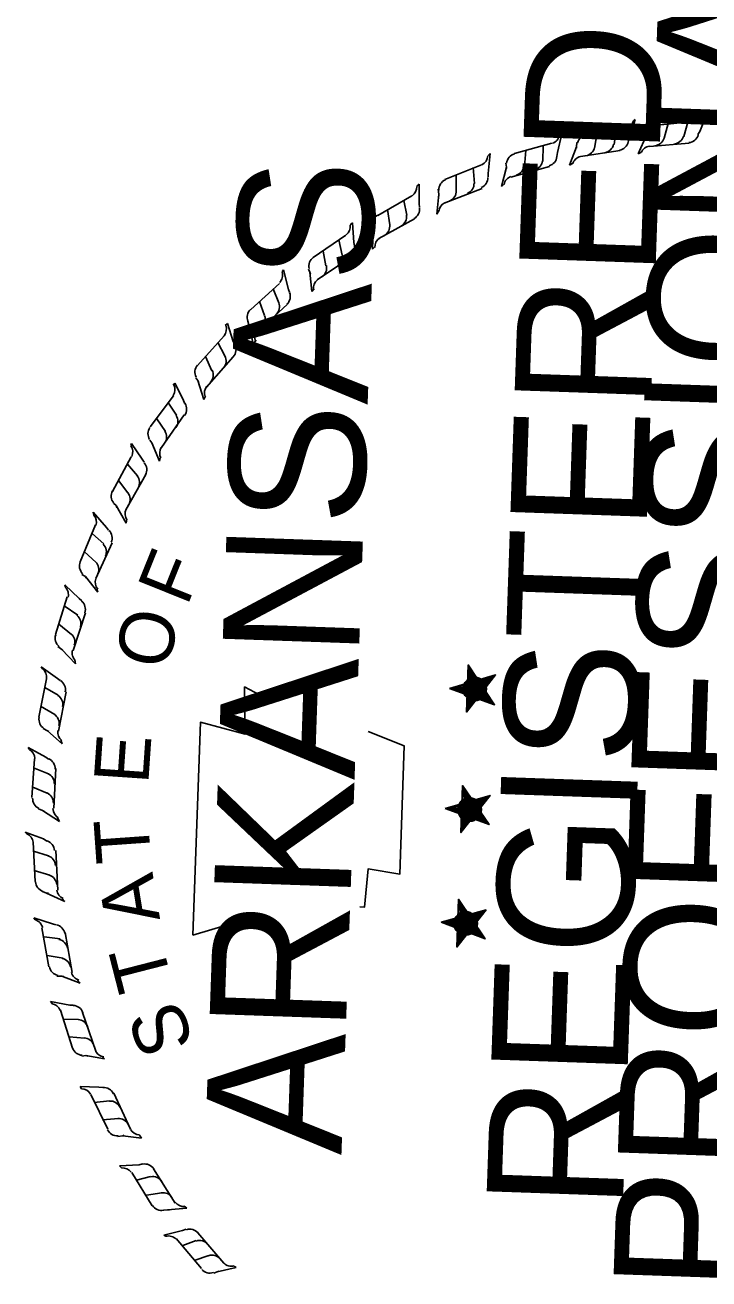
# Model space of a CAD drawing. Extents: x 634032 to 635126, y 289804 to 291423.
# Drawn here: x 634402.1 to 634451.4, y 289860.1 to 289950.5 of the extents above; entities that cross this region are included whole.
import ezdxf

# ---------------------------------------------------------------- set-up
doc = ezdxf.new("R2010")
doc.units = 0
doc.layers.add('Level 1', color=7, linetype='Continuous')

msp = doc.modelspace()

# ---------------------------------------------------------------- linework, layer by layer
at = {"layer": 'Level 1'}
for p, q in [((634445.657, 289942.332), (634446.054, 289943.669)), ((634446.054, 289943.669), (634445.951, 289943.573)), ((634447.641, 289943.264), (634450.503, 289943.564)), ((634449.563, 289942.446), (634449.85, 289943.487)), ((634450.727, 289942.806), (634451.222, 289944.089)), ((634451.222, 289944.089), (634451.072, 289944.094)), ((634440.468, 289941.313), (634440.765, 289942.653)), ((634440.765, 289942.653), (634440.612, 289942.558)), ((634442.614, 289942.589), (634445.382, 289943.042)), ((634443.131, 289941.62), (634443.319, 289942.714)), ((634444.54, 289941.871), (634444.679, 289942.967)), ((634446.865, 289942.54), (634446.268, 289941.21)), ((634446.865, 289942.54), (634446.86, 289942.39)), ((634446.874, 289942.79), (634446.865, 289942.54)), ((634448.159, 289942.345), (634448.446, 289943.386)), ((634450.57, 289942.611), (634450.727, 289942.806)), ((634437.363, 289941.221), (634440.041, 289941.978)), ((634439.395, 289940.65), (634439.435, 289941.799)), ((634441.833, 289941.715), (634441.336, 289940.382)), ((634441.833, 289941.715), (634441.83, 289941.615)), ((634441.844, 289942.015), (634441.833, 289941.715)), ((634445.548, 289942.086), (634445.657, 289942.332)), ((634449.947, 289941.982), (634447.087, 289941.732)), ((634435.613, 289941.232), (634435.457, 289941.087)), ((634435.462, 289939.786), (634435.613, 289941.232)), ((634438.081, 289940.295), (634438.171, 289941.443)), ((634440.408, 289941.015), (634440.468, 289941.313)), ((634444.976, 289941.455), (634442.109, 289941.005)), ((634446.268, 289941.21), (634446.472, 289941.303)), ((634432.345, 289939.345), (634434.983, 289940.404)), ((634434.486, 289939.07), (634434.377, 289940.225)), ((634436.779, 289940.241), (634436.43, 289938.852)), ((634436.739, 289940.542), (634436.779, 289940.241)), ((634436.779, 289940.241), (634436.775, 289940.141)), ((634439.882, 289940.282), (634437.104, 289939.529)), ((634441.336, 289940.382), (634441.591, 289940.523)), ((634430.482, 289939.01), (634430.327, 289938.865)), ((634430.483, 289937.609), (634430.482, 289939.01)), ((634433.166, 289938.516), (634433.158, 289939.717)), ((634435.453, 289939.537), (634435.462, 289939.786)), ((634436.43, 289938.852), (634436.637, 289939.045)), ((634427.502, 289936.762), (634429.953, 289938.178)), ((634431.908, 289938.31), (634431.758, 289936.864)), ((634431.871, 289938.661), (634431.908, 289938.31)), ((634431.908, 289938.31), (634431.903, 289938.16)), ((634435.024, 289938.701), (634432.285, 289937.646)), ((634428.378, 289936.081), (634428.217, 289937.188)), ((634429.604, 289936.789), (634429.391, 289937.847)), ((634430.524, 289937.357), (634430.483, 289937.609)), ((634425.682, 289936.226), (634425.527, 289936.081)), ((634425.783, 289934.821), (634425.682, 289936.226)), ((634430.145, 289936.52), (634427.594, 289935.108)), ((634431.758, 289936.864), (634431.916, 289937.109)), ((634422.843, 289933.723), (634425.201, 289935.342)), ((634427.074, 289935.977), (634427.165, 289935.724)), ((634427.165, 289935.724), (634427.116, 289934.324)), ((634427.165, 289935.724), (634427.16, 289935.574)), ((634424.95, 289933.9), (634424.689, 289935.01)), ((634425.824, 289934.57), (634425.783, 289934.821)), ((634427.116, 289934.324), (634427.323, 289934.517)), ((634425.545, 289933.729), (634423.137, 289932.112)), ((634423.773, 289933.14), (634423.56, 289934.198)), ((634420.711, 289932.847), (634420.606, 289932.701)), ((634421.062, 289931.434), (634420.711, 289932.847)), ((634422.513, 289932.884), (634422.606, 289932.681)), ((634422.606, 289932.681), (634422.757, 289931.275)), ((634422.606, 289932.681), (634422.651, 289932.529)), ((634418.359, 289929.977), (634420.426, 289931.856)), ((634420.377, 289930.457), (634419.962, 289931.472)), ((634421.155, 289931.231), (634421.062, 289931.434)), ((634422.757, 289931.275), (634422.914, 289931.469)), ((634420.973, 289930.336), (634418.803, 289928.361)), ((634419.345, 289929.543), (634418.98, 289930.556)), ((634416.674, 289928.986), (634416.518, 289928.841)), ((634417.078, 289927.671), (634416.674, 289928.986)), ((634418.13, 289929.135), (634418.221, 289928.881)), ((634414.517, 289925.959), (634416.442, 289928.093)), ((634418.221, 289928.881), (634418.524, 289927.52)), ((634418.221, 289928.881), (634418.316, 289928.728)), ((634416.492, 289926.64), (634415.975, 289927.609)), ((634417.221, 289927.466), (634417.078, 289927.671)), ((634418.524, 289927.52), (634418.732, 289927.763)), ((634415.554, 289925.573), (634415.089, 289926.589)), ((634417.09, 289926.57), (634415.162, 289924.386)), ((634412.871, 289924.666), (634412.765, 289924.519)), ((634413.48, 289923.494), (634412.871, 289924.666)), ((634414.385, 289925.063), (634414.528, 289924.858)), ((634414.528, 289924.858), (634414.981, 289923.491)), ((634414.528, 289924.858), (634414.575, 289924.756)), ((634411.11, 289921.525), (634412.789, 289923.768)), ((634414.981, 289923.491), (634415.09, 289923.738)), ((634412.99, 289922.36), (634412.42, 289923.23)), ((634413.571, 289923.24), (634413.48, 289923.494)), ((634412.199, 289921.187), (634411.581, 289922.109)), ((634413.542, 289922.391), (634411.909, 289920.046)), ((634409.767, 289920.321), (634409.712, 289920.173)), ((634410.528, 289919.194), (634409.767, 289920.321)), ((634411.077, 289920.576), (634411.22, 289920.371)), ((634411.22, 289920.371), (634411.774, 289919.051)), ((634411.22, 289920.371), (634411.266, 289920.269)), ((634408.396, 289916.867), (634409.734, 289919.372)), ((634410.671, 289918.989), (634410.528, 289919.194)), ((634411.774, 289919.051), (634411.833, 289919.299)), ((634410.186, 289918.005), (634409.465, 289918.831)), ((634409.493, 289916.779), (634408.823, 289917.653)), ((634410.79, 289918.084), (634409.35, 289915.533)), ((634408.466, 289916.014), (634408.661, 289915.857)), ((634408.661, 289915.857), (634409.366, 289914.582)), ((634408.661, 289915.857), (634408.705, 289915.706)), ((634407.955, 289914.281), (634406.992, 289915.365)), ((634406.992, 289915.365), (634407.035, 289915.164)), ((634409.366, 289914.582), (634409.427, 289914.88)), ((634406.067, 289911.795), (634407.161, 289914.459)), ((634407.763, 289913.087), (634406.938, 289913.816)), ((634408.098, 289914.076), (634407.955, 289914.281)), ((634408.366, 289913.166), (634407.176, 289910.606)), ((634407.217, 289911.755), (634406.343, 289912.536)), ((634405.975, 289909.147), (634404.959, 289910.133)), ((634404.959, 289910.133), (634405.003, 289909.981)), ((634406.186, 289910.891), (634406.43, 289910.732)), ((634406.43, 289910.732), (634407.341, 289909.599)), ((634406.43, 289910.732), (634406.477, 289910.63)), ((634404.283, 289906.554), (634405.129, 289909.276)), ((634406.169, 289908.99), (634405.975, 289909.147)), ((634407.341, 289909.599), (634407.25, 289909.853)), ((634405.883, 289907.949), (634404.906, 289908.634)), ((634405.434, 289906.564), (634404.509, 289907.297)), ((634406.44, 289908.13), (634405.544, 289905.41)), ((634404.453, 289905.698), (634404.746, 289905.488)), ((634404.746, 289905.488), (634405.711, 289904.453)), ((634404.746, 289905.488), (634404.795, 289905.436)), ((634405.711, 289904.453), (634405.67, 289904.705)), ((634404.423, 289903.398), (634403.252, 289904.239)), ((634403.252, 289904.239), (634403.347, 289904.085)), ((634434.025, 289904.365), (634434.514, 289902.597)), ((634434.025, 289904.365), (634434.071, 289902.812)), ((634434.025, 289904.365), (634434.176, 289902.959)), ((634434.025, 289904.365), (634434.276, 289902.955)), ((634434.025, 289904.365), (634434.386, 289903.252)), ((634434.025, 289904.365), (634434.49, 289903.348)), ((634434.025, 289904.365), (634434.541, 289903.396)), ((634403.074, 289900.593), (634403.622, 289903.375)), ((634404.618, 289903.241), (634404.423, 289903.398)), ((634432.665, 289902.661), (634433.928, 289903.018)), ((634432.665, 289902.661), (634433.924, 289902.918)), ((634436.001, 289903.646), (634434.514, 289902.597)), ((634436.001, 289903.646), (634434.527, 289902.997)), ((634436.001, 289903.646), (634434.533, 289903.147)), ((634436.001, 289903.646), (634434.727, 289902.99)), ((634436.001, 289903.646), (634434.913, 289902.583)), ((634436.001, 289903.646), (634434.92, 289902.783)), ((634436.001, 289903.646), (634435.063, 289902.578)), ((634404.481, 289902.195), (634403.499, 289902.729)), ((634405.04, 289902.425), (634404.49, 289899.593)), ((634432.665, 289902.661), (634433.919, 289902.768)), ((634434.514, 289902.597), (634432.665, 289902.661)), ((634432.665, 289902.661), (634433.912, 289902.568)), ((634432.665, 289902.661), (634433.909, 289902.468)), ((634432.665, 289902.661), (634433.905, 289902.368)), ((634433.906, 289900.967), (634434.514, 289902.597)), ((634433.906, 289900.967), (634434.05, 289902.213)), ((634433.906, 289900.967), (634434.15, 289902.209)), ((634433.906, 289900.967), (634434.246, 289902.106)), ((634433.906, 289900.967), (634434.396, 289902.101)), ((634433.906, 289900.967), (634434.494, 289902.047)), ((634433.906, 289900.967), (634434.644, 289902.042)), ((634435.926, 289901.497), (634434.514, 289902.597)), ((634435.926, 289901.497), (634434.596, 289902.094)), ((634435.926, 289901.497), (634434.699, 289902.19)), ((634435.926, 289901.497), (634434.753, 289902.288)), ((634435.926, 289901.497), (634434.908, 289902.433)), ((634435.926, 289901.497), (634434.913, 289902.583)), ((634435.926, 289901.497), (634435.015, 289902.629)), ((634404.232, 289900.803), (634403.202, 289901.389)), ((634403.396, 289899.781), (634403.691, 289899.621)), ((634403.691, 289899.621), (634404.759, 289898.683)), ((634403.691, 289899.621), (634403.789, 289899.567)), ((634403.575, 289897.724), (634402.298, 289898.419)), ((634402.298, 289898.419), (634402.393, 289898.265)), ((634404.759, 289898.683), (634404.668, 289898.936)), ((634402.572, 289894.807), (634402.77, 289897.602)), ((634403.769, 289897.567), (634403.575, 289897.724)), ((634403.783, 289896.516), (634402.697, 289896.954)), ((634404.296, 289896.898), (634404.147, 289894.051)), ((634403.684, 289895.118), (634402.648, 289895.555)), ((634433.621, 289895.674), (634434.112, 289893.956)), ((634433.621, 289895.674), (634433.669, 289894.171)), ((634433.621, 289895.674), (634433.872, 289894.264)), ((634433.621, 289895.674), (634433.922, 289894.262)), ((634433.621, 289895.674), (634434.083, 289894.557)), ((634433.621, 289895.674), (634434.086, 289894.657)), ((634433.621, 289895.674), (634434.188, 289894.703)), ((634435.597, 289894.954), (634434.112, 289893.956)), ((634435.597, 289894.954), (634434.174, 289894.304)), ((634435.597, 289894.954), (634434.179, 289894.454)), ((634435.597, 289894.954), (634434.424, 289894.295)), ((634435.597, 289894.954), (634434.56, 289893.89)), ((634435.597, 289894.954), (634434.567, 289894.09)), ((634435.597, 289894.954), (634434.66, 289893.886)), ((634403.044, 289893.99), (634403.34, 289893.879)), ((634403.34, 289893.879), (634404.563, 289893.086)), ((634403.34, 289893.879), (634403.439, 289893.826)), ((634432.363, 289894.017), (634433.574, 289894.325)), ((634432.363, 289894.017), (634433.571, 289894.225)), ((634432.363, 289894.017), (634433.566, 289894.075)), ((634434.112, 289893.956), (634432.363, 289894.017)), ((634432.363, 289894.017), (634433.559, 289893.875)), ((634432.363, 289894.017), (634433.555, 289893.775)), ((634432.363, 289894.017), (634433.502, 289893.677)), ((634433.503, 289892.276), (634434.112, 289893.956)), ((634435.524, 289892.856), (634434.112, 289893.956)), ((634435.524, 289892.856), (634434.51, 289893.892)), ((634435.524, 289892.856), (634434.554, 289893.74)), ((634435.524, 289892.856), (634434.661, 289893.936)), ((634404.563, 289893.086), (634404.422, 289893.341)), ((634433.503, 289892.276), (634433.696, 289893.52)), ((634433.503, 289892.276), (634433.794, 289893.466)), ((634433.503, 289892.276), (634433.844, 289893.465)), ((634433.503, 289892.276), (634434.043, 289893.408)), ((634433.503, 289892.276), (634434.191, 289893.353)), ((634433.503, 289892.276), (634434.291, 289893.349)), ((634435.524, 289892.856), (634434.194, 289893.452)), ((634435.524, 289892.856), (634434.396, 289893.495)), ((634435.524, 289892.856), (634434.399, 289893.595)), ((634403.419, 289891.826), (634402.085, 289892.322)), ((634402.085, 289892.322), (634402.23, 289892.167)), ((634402.811, 289888.745), (634402.66, 289891.602)), ((634403.663, 289891.667), (634403.419, 289891.826)), ((634403.777, 289890.612), (634402.688, 289890.95)), ((634404.29, 289890.995), (634404.441, 289888.138)), ((634403.878, 289889.208), (634402.739, 289889.548)), ((634403.336, 289888.026), (634403.632, 289887.916)), ((634403.632, 289887.916), (634404.962, 289887.319)), ((634403.632, 289887.916), (634403.782, 289887.91)), ((634404.962, 289887.319), (634404.769, 289887.526)), ((634433.335, 289887.479), (634433.826, 289885.761)), ((634433.335, 289887.479), (634433.383, 289885.976)), ((634433.335, 289887.479), (634433.586, 289886.069)), ((634433.335, 289887.479), (634433.636, 289886.067)), ((634433.335, 289887.479), (634433.797, 289886.362)), ((634433.335, 289887.479), (634433.8, 289886.462)), ((634433.335, 289887.479), (634433.902, 289886.508)), ((634435.31, 289886.709), (634433.826, 289885.761)), ((634435.31, 289886.709), (634433.888, 289886.109)), ((634435.31, 289886.709), (634433.891, 289886.209)), ((634435.31, 289886.709), (634434.136, 289886.05)), ((634435.31, 289886.709), (634434.275, 289885.745)), ((634435.31, 289886.709), (634434.281, 289885.895)), ((634435.31, 289886.709), (634434.375, 289885.741)), ((634404.055, 289885.7), (634402.72, 289886.146)), ((634402.72, 289886.146), (634402.815, 289885.993)), ((634404.303, 289885.641), (634404.055, 289885.7)), ((634432.077, 289885.822), (634433.286, 289886.08)), ((634432.077, 289885.822), (634433.283, 289885.98)), ((634432.077, 289885.822), (634433.279, 289885.88)), ((634433.826, 289885.761), (634432.077, 289885.822)), ((634432.077, 289885.822), (634433.272, 289885.68)), ((634432.077, 289885.822), (634433.269, 289885.58)), ((634432.077, 289885.822), (634433.215, 289885.482)), ((634433.215, 289884.031), (634433.826, 289885.761)), ((634435.236, 289884.611), (634433.826, 289885.761)), ((634435.236, 289884.611), (634434.225, 289885.747)), ((634435.236, 289884.611), (634434.375, 289885.741)), ((634403.797, 289882.607), (634403.295, 289885.426)), ((634404.618, 289884.629), (634403.472, 289884.769)), ((634404.984, 289885.067), (634405.484, 289882.198)), ((634433.215, 289884.031), (634433.408, 289885.275)), ((634433.215, 289884.031), (634433.508, 289885.271)), ((634433.215, 289884.031), (634433.556, 289885.22)), ((634433.215, 289884.031), (634433.756, 289885.213)), ((634433.215, 289884.031), (634433.906, 289885.207)), ((634433.215, 289884.031), (634434.006, 289885.204)), ((634435.236, 289884.611), (634433.906, 289885.207)), ((634435.236, 289884.611), (634434.11, 289885.3)), ((634435.236, 289884.611), (634434.113, 289885.4)), ((634435.236, 289884.611), (634434.268, 289885.545)), ((634404.819, 289883.221), (634403.675, 289883.411)), ((634404.374, 289881.936), (634404.724, 289881.924)), ((634404.724, 289881.924), (634406.057, 289881.427)), ((634404.724, 289881.924), (634404.874, 289881.919)), ((634406.057, 289881.427), (634405.864, 289881.634)), ((634405.302, 289879.852), (634403.91, 289880.101)), ((634403.91, 289880.101), (634404.054, 289879.946)), ((634405.494, 289876.744), (634404.638, 289879.475)), ((634405.552, 289879.844), (634405.302, 289879.852)), ((634406.234, 289879.32), (634407.187, 289876.535)), ((634405.917, 289878.83), (634404.816, 289878.819)), ((634406.369, 289877.464), (634405.272, 289877.552)), ((634406.174, 289876.17), (634406.476, 289876.209)), ((634406.476, 289876.209), (634407.818, 289875.962)), ((634406.476, 289876.209), (634406.624, 289876.154)), ((634407.818, 289875.962), (634407.673, 289876.117)), ((634407.396, 289873.926), (634406.047, 289873.973)), ((634406.047, 289873.973), (634406.142, 289873.82)), ((634407.696, 289873.915), (634407.396, 289873.926)), ((634408.041, 289870.901), (634406.828, 289873.395)), ((634408.163, 289872.948), (634407.058, 289872.837)), ((634408.482, 289873.488), (634409.692, 289870.894)), ((634408.819, 289871.675), (634407.664, 289871.565)), ((634408.773, 289870.376), (634409.125, 289870.413)), ((634409.125, 289870.413), (634409.227, 289870.46)), ((634409.125, 289870.413), (634410.471, 289870.266)), ((634410.471, 289870.266), (634410.328, 289870.471)), ((634410.303, 289868.321), (634408.9, 289868.27)), ((634408.9, 289868.27), (634409.045, 289868.115)), ((634411.251, 289865.386), (634409.784, 289867.789)), ((634410.556, 289868.412), (634410.303, 289868.321)), ((634411.343, 289868.034), (634412.908, 289865.578)), ((634411.124, 289867.492), (634410.114, 289867.227)), ((634411.933, 289866.313), (634410.827, 289866.151)), ((634412.09, 289865.057), (634412.341, 289865.098)), ((634412.341, 289865.098), (634413.746, 289865.199)), ((634412.341, 289865.098), (634412.491, 289865.093)), ((634413.746, 289865.199), (634413.551, 289865.356)), ((634413.44, 289863.609), (634412.077, 289863.256)), ((634412.077, 289863.256), (634412.225, 289863.201)), ((634414.795, 289860.86), (634412.969, 289863.025)), ((634413.693, 289863.7), (634413.44, 289863.609)), ((634414.534, 289863.42), (634416.41, 289861.254)), ((634414.415, 289862.874), (634413.452, 289862.508)), ((634415.328, 289861.792), (634414.264, 289861.428)), ((634415.684, 289860.528), (634415.937, 289860.62)), ((634415.937, 289860.62), (634417.299, 289860.922)), ((634415.937, 289860.62), (634416.039, 289860.666)), ((634417.299, 289860.922), (634417.152, 289861.027))]:
    msp.add_line(p, q, dxfattribs=at)
for points in [[(634432.665, 289902.661), (634436.001, 289903.646), (634433.906, 289900.967), (634434.025, 289904.365), (634435.926, 289901.497), (634432.665, 289902.661)], [(634419.334, 289902.026), (634417.91, 289902.776), (634417.941, 289899.373), (634414.719, 289900.236), (634414.183, 289884.896)], [(634426.212, 289886.927), (634426.561, 289886.915), (634426.807, 289889.658), (634429.095, 289889.278), (634429.418, 289898.522), (634426.803, 289899.564)], [(634432.363, 289894.017), (634435.597, 289894.954), (634433.503, 289892.276), (634433.621, 289895.674), (634435.524, 289892.856), (634432.363, 289894.017)], [(634432.077, 289885.822), (634435.31, 289886.709), (634433.215, 289884.031), (634433.335, 289887.479), (634435.236, 289884.611), (634432.077, 289885.822)], [(634414.183, 289884.896), (634418.278, 289886.103)]]:
    msp.add_lwpolyline(points, dxfattribs=at)
for centre, radius in [((634434.49, 289902.631), 0.848), ((634434.49, 289902.631), 0.767), ((634434.49, 289902.631), 0.711), ((634434.49, 289902.631), 0.653), ((634434.49, 289902.631), 0.57), ((634434.49, 289902.631), 0.529), ((634434.49, 289902.631), 0.488), ((634434.49, 289902.631), 0.42), ((634434.49, 289902.631), 0.368), ((634434.49, 289902.631), 0.306), ((634434.49, 289902.631), 0.244), ((634434.49, 289902.631), 0.182), ((634434.49, 289902.631), 0.146), ((634434.49, 289902.631), 0.071), ((634434.129, 289893.941), 0.848), ((634434.129, 289893.941), 0.767), ((634434.129, 289893.941), 0.711), ((634434.129, 289893.941), 0.653), ((634434.129, 289893.941), 0.57), ((634434.129, 289893.941), 0.529), ((634434.129, 289893.941), 0.488), ((634434.129, 289893.941), 0.42), ((634434.129, 289893.941), 0.368), ((634434.129, 289893.941), 0.306), ((634434.129, 289893.941), 0.244), ((634434.129, 289893.941), 0.182), ((634434.129, 289893.941), 0.146), ((634434.129, 289893.941), 0.071), ((634433.842, 289885.732), 0.848), ((634433.842, 289885.732), 0.767), ((634433.842, 289885.732), 0.711), ((634433.842, 289885.732), 0.653), ((634433.842, 289885.732), 0.57), ((634433.842, 289885.732), 0.529), ((634433.842, 289885.732), 0.488), ((634433.842, 289885.732), 0.42), ((634433.842, 289885.732), 0.368), ((634433.842, 289885.732), 0.306), ((634433.842, 289885.732), 0.244), ((634433.842, 289885.732), 0.182), ((634433.842, 289885.732), 0.146), ((634433.842, 289885.732), 0.071)]:
    msp.add_circle(centre, radius, dxfattribs=at)
for centre, start, end in [((634445.176, 289943.815), 283.79119, 342.57904), ((634450.354, 289944.332), 279.43481, 338.22265), ((634439.84, 289942.699), 290.09384, 348.88168), ((634442.673, 289941.836), 99.53042, 167.90439), ((634447.708, 289942.548), 95.17403, 163.548), ((634449.862, 289942.786), 275.17403, 343.548), ((634442.371, 289941.83), 279.53042, 347.90439), ((634443.74, 289942.055), 279.53042, 347.90439), ((634444.802, 289942.236), 279.53042, 347.90439), ((634447.216, 289941.002), 99.43481, 158.22265), ((634447.406, 289942.566), 275.17403, 343.548), ((634448.789, 289942.685), 275.17403, 343.548), ((634434.662, 289941.114), 297.14508, 355.93292), ((634437.57, 289940.456), 105.83306, 174.20703), ((634439.643, 289941.088), 285.83306, 354.20703), ((634442.3, 289940.257), 103.79119, 162.57904), ((634437.27, 289940.418), 285.83306, 354.20703), ((634438.607, 289940.791), 285.83306, 354.20703), ((634432.685, 289938.61), 112.8843, 181.25827), ((634433.672, 289939.07), 292.8843, 1.25827), ((634434.664, 289939.492), 292.8843, 1.25827), ((634437.372, 289938.846), 110.09384, 168.88168), ((634429.543, 289938.823), 304.00344, 2.79128), ((634432.391, 289938.535), 292.8843, 1.25827), ((634429.738, 289937.212), 299.74266, 8.11663), ((634432.686, 289936.988), 117.14508, 175.93292), ((634427.878, 289936.101), 119.74266, 188.11663), ((634428.804, 289936.675), 299.74266, 8.11663), ((634424.739, 289935.964), 308.95049, 7.73834), ((634427.596, 289935.991), 299.74266, 8.11663), ((634425.072, 289934.376), 304.68972, 13.06369), ((634428.073, 289934.49), 124.00344, 182.79128), ((634423.316, 289933.108), 124.68972, 193.06369), ((634424.188, 289933.76), 304.68972, 13.06369), ((634419.869, 289932.454), 317.22624, 16.01408), ((634423.044, 289932.975), 304.68972, 13.06369), ((634423.649, 289931.52), 128.95049, 187.73834), ((634420.428, 289930.931), 312.96546, 21.33943), ((634418.872, 289929.423), 132.96546, 201.33943), ((634419.641, 289930.194), 312.96546, 21.33943), ((634418.622, 289929.252), 312.96546, 21.33943), ((634415.82, 289928.564), 322.451, 21.23884), ((634419.43, 289927.9), 137.22624, 196.01408), ((634416.515, 289927.098), 318.19023, 26.5642), ((634415.798, 289926.293), 318.19023, 26.5642), ((634415.102, 289925.455), 138.19023, 206.5642), ((634414.869, 289925.262), 318.19023, 26.5642), ((634412.109, 289924.191), 328.43436, 27.22221), ((634415.797, 289923.989), 142.451, 201.23884), ((634412.952, 289922.805), 324.17359, 32.54756), ((634412.324, 289921.93), 324.17359, 32.54756), ((634411.719, 289921.024), 144.17359, 212.54756), ((634411.507, 289920.808), 324.17359, 32.54756), ((634409.073, 289919.723), 335.33158, 34.11942), ((634412.563, 289919.638), 148.43436, 207.22221), ((634410.077, 289918.449), 331.0708, 39.44478), ((634409.559, 289917.504), 331.0708, 39.44478), ((634409.067, 289916.532), 151.0708, 219.44478), ((634408.883, 289916.292), 331.0708, 39.44478), ((634410.071, 289915.258), 155.33158, 214.11942), ((634406.452, 289914.67), 341.35627, 40.14411), ((634407.584, 289913.508), 337.09549, 45.46946), ((634407.168, 289912.514), 337.09549, 45.46946), ((634406.781, 289911.496), 157.09549, 225.46946), ((634406.623, 289911.237), 337.09549, 45.46946), ((634407.913, 289910.334), 161.35627, 220.14411), ((634404.431, 289909.43), 346.25171, 45.03955), ((634405.658, 289908.369), 341.99093, 50.3649), ((634405.328, 289907.343), 341.99093, 50.3649), ((634405.029, 289906.295), 161.99093, 230.3649), ((634404.894, 289906.024), 341.99093, 50.3649), ((634406.257, 289905.234), 166.25171, 225.03955), ((634402.864, 289903.469), 353.68385, 52.47169), ((634404.219, 289902.576), 349.42307, 57.79704), ((634404.024, 289901.515), 349.42307, 57.79704), ((634403.863, 289900.438), 169.42307, 237.79704), ((634403.764, 289900.152), 349.42307, 57.79704), ((634405.217, 289899.545), 173.68385, 232.47169), ((634402.008, 289897.596), 1.42361, 60.21146), ((634403.47, 289896.893), 357.16284, 65.53681), ((634403.42, 289895.816), 357.16284, 65.53681), ((634403.406, 289894.728), 177.16284, 245.53681), ((634403.346, 289894.431), 357.16284, 65.53681), ((634404.868, 289894.025), 181.42361, 240.21146), ((634401.901, 289891.473), 7.92492, 66.71276), ((634403.434, 289890.94), 3.66414, 72.03812), ((634403.506, 289889.865), 3.66414, 72.03812), ((634403.589, 289888.48), 3.66414, 72.03812), ((634403.615, 289888.782), 183.66414, 252.03812), ((634405.147, 289888.249), 187.92492, 246.71276), ((634402.6, 289885.237), 14.27006, 73.0579), ((634404.182, 289884.877), 10.00928, 78.38325), ((634404.372, 289883.816), 10.00928, 78.38325), ((634404.608, 289882.449), 10.00928, 78.38325), ((634404.601, 289882.751), 190.00928, 258.38325), ((634406.182, 289882.391), 194.27006, 253.0579), ((634403.9, 289879.168), 22.83706, 81.62491), ((634405.518, 289879.047), 18.57629, 86.95026), ((634405.864, 289878.026), 18.57629, 86.95026), ((634406.301, 289876.709), 18.57629, 86.95026), ((634406.248, 289877.007), 198.57629, 266.95026), ((634407.866, 289876.887), 202.83706, 261.62491), ((634407.752, 289873.125), 25.69371, 94.06769), ((634406.132, 289873.044), 29.95449, 88.74233), ((634408.223, 289872.155), 25.69371, 94.06769), ((634408.82, 289870.902), 25.69371, 94.06769), ((634408.73, 289871.192), 205.69371, 274.06769), ((634410.351, 289871.273), 209.95449, 268.74233), ((634409.11, 289867.335), 37.11353, 95.90138), ((634410.707, 289867.617), 32.85276, 101.22673), ((634411.295, 289866.714), 32.85276, 101.22673), ((634412.043, 289865.545), 32.85276, 101.22673), ((634411.918, 289865.821), 212.85276, 281.22673), ((634413.516, 289866.103), 217.11353, 275.90138), ((634412.421, 289862.429), 44.82348, 103.61132), ((634413.967, 289862.923), 40.5627, 108.93667), ((634414.67, 289862.106), 40.5627, 108.93667), ((634415.568, 289861.048), 40.5627, 108.93667), ((634416.953, 289861.799), 224.82348, 283.61132), ((634415.408, 289861.305), 220.5627, 288.93667)]:
    msp.add_arc(centre, 0.777, start, end, dxfattribs=at)

# ---------------------------------------------------------------- texts
for s, height, rotation, p in [('PROFESSIONAL', 9.8421, 88, (634454.305, 289859.03)), ('REGISTERED', 9.8421, 88, (634445.158, 289865.002)), ('ARKANSAS', 9.8421, 88, (634424.886, 289869.012)), ('F', 3.936, 68.07066, (634413.758, 289908.525)), ('O', 3.936, 78.4515, (634412.396, 289903.92)), ('E', 3.937, 86.07323, (634410.959, 289895.715)), ('T', 3.937, 94.02276, (634411.167, 289890.204)), ('A', 3.937, 99.21318, (634411.821, 289886.029)), ('T', 3.937, 104.4036, (634412.712, 289881.445)), ('S', 3.937, 109.59401, (634414.309, 289877.036))]:
    msp.add_text(s, height=height, rotation=rotation, dxfattribs=at).set_placement(p)

doc.saveas('drawing.dxf')
